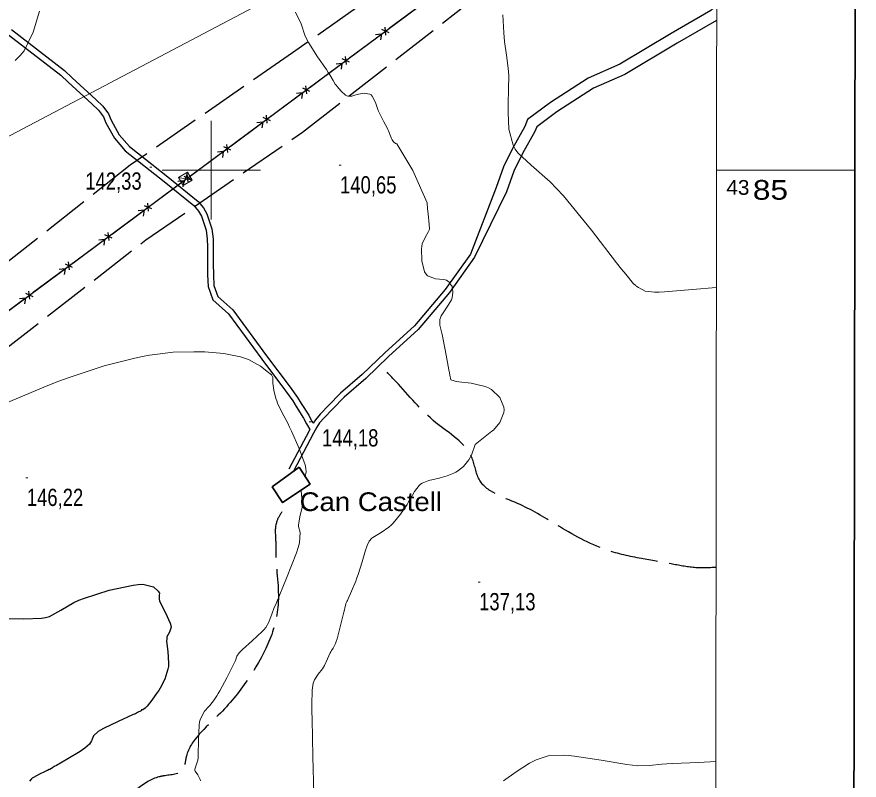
# Model space of a CAD drawing. Extents: x 487425 to 492029, y 4383576 to 4386788.
# Drawn here: x 490901.3 to 491328.9, y 4384690.4 to 4385077.8 of the extents above; entities that cross this region are included whole.
import ezdxf

# ---------------------------------------------------------------- set-up
doc = ezdxf.new("R2010")
doc.units = 0
doc.header["$LTSCALE"] = 4
doc.linetypes.add('DOTTED', pattern=[1.5, 0.3, -1.2])
doc.linetypes.add('LONG_DASHED', pattern=[7.5, 6, -1.5])
for name, color, linetype, lineweight in [('1', 7, 'Continuous', 13), ('2', 7, 'DOTTED', 13), ('24', 7, 'Continuous', 13), ('26', 7, 'LONG_DASHED', 25), ('27', 7, 'Continuous', 25), ('38', 7, 'Continuous', 25), ('43', 7, 'Continuous', 25), ('47', 7, 'Continuous', 35), ('7', 7, 'Continuous', 13), ('8', 7, 'Continuous', 25), ('9', 7, 'Continuous', 13)]:
    doc.layers.add(name, color=color, linetype=linetype, lineweight=lineweight)
doc.layers.add('5', color=7, linetype='Continuous')

msp = doc.modelspace()

# ---------------------------------------------------------------- linework, layer by layer
at = {"layer": '1'}
for p, q in [((491000, 4385025), (491000, 4384975)), ((490975, 4385000), (491025, 4385000)), ((491256.46, 4385000), (491326.67, 4385000))]:
    msp.add_line(p, q, dxfattribs=at)
at = {"layer": '1', "lineweight": 35}
msp.add_lwpolyline([(487611.46, 4386512.7), (491328.86, 4386507.3), (491325.3, 4384052.3), (487607.9, 4384057.7)], close=True, dxfattribs=at)
at = {"layer": '1'}
msp.add_lwpolyline([(487681.9, 4386441.2), (491258.2, 4386436), (491255.4, 4384123.8), (487678, 4384129)], close=True, dxfattribs=at)
at = {"layer": '24'}
msp.add_lwpolyline([(488954.49, 4384817.11), (489198.5, 4384851.16), (489357.39, 4384873.86), (489601.4, 4384907.91), (489794.34, 4384879.53), (490083.75, 4384822.79), (490248.31, 4384800.09), (490395.85, 4384817.11), (490526.37, 4384822.79), (490764.71, 4384947.63), (491088.16, 4385117.87), (491252.72, 4385202.99), (491256.7, 4385199.2)], dxfattribs=at)
at = {"layer": '26'}
for points in [[(491256.66, 4385212.94), (491193.79, 4385169.68), (491122.92, 4385116.81), (491041.24, 4385059.54), (490958.82, 4385002.51), (490860.74, 4384924.98), (490760.29, 4384859), (490692.5, 4384806.79), (490609.37, 4384741.58), (490560.51, 4384697.87)], [(490600.09, 4384693.63), (490616.48, 4384709.55), (490676.36, 4384751.65), (490767.73, 4384815.34), (490869.55, 4384889.03), (490966.8, 4384964.62), (491046.3, 4385019.26), (491131.3, 4385085.44), (491213.14, 4385147.42), (491256.63, 4385183.39)]]:
    msp.add_lwpolyline(points, dxfattribs=at)
at = {"layer": '27'}
msp.add_spline([(490552.62, 4384941.58), (490554.42, 4384943.67), (490554.9, 4384950.57), (490551.02, 4384958.75), (490549.23, 4384963.11), (490546.55, 4384969.04), (490546.27, 4384975.56), (490577.59, 4384991.51), (490608.31, 4385010.39), (490640.99, 4385029.26), (490675.61, 4385047.83), (490715.19, 4385070.58), (490756.65, 4385095.72), (490790.53, 4385116.54), (490822.22, 4385132.71), (490831.7, 4385141.3), (490834.32, 4385140.92), (490836.94, 4385139.04), (490838.42, 4385134.39), (490839.83, 4385127.26), (490841.17, 4385124.33), (490843.93, 4385120.95), (490854.88, 4385120.69), (490881, 4385131.56), (490910.74, 4385145.49), (490944, 4385160.61), (490977.26, 4385174.31), (491011.8, 4385191.9), (491038.91, 4385205.09), (491047.85, 4385210.16), (491048.16, 4385215.03), (491046.15, 4385220.51), (491027.8, 4385249.96), (491013.09, 4385271.3), (490994.07, 4385304.34), (490984.67, 4385319.67), (490979.29, 4385327.18), (490976.61, 4385330.57), (490974.75, 4385335.52), (490975.45, 4385343.54), (490977.85, 4385344.21), (490979.42, 4385344.13), (490980.47, 4385343.6), (490983.46, 4385341.64), (490988.77, 4385336.68), (490990.42, 4385334.95), (490993.78, 4385332.31), (491019.1, 4385348.81), (491045.47, 4385366.05), (491074.68, 4385380.36), (491106.91, 4385400.5), (491123.13, 4385410.28), (491127.87, 4385413.64), (491130.35, 4385415.43), (491144.45, 4385391.54), (491161.89, 4385359.02), (491165.47, 4385353.38)], degree=3, dxfattribs=at)
at = {"layer": '38'}
msp.add_line((491256.55, 4385076.09), (491256.5, 4385076.06), dxfattribs=at)
at = {"layer": '38', "linetype": 'LONG_DASHED'}
msp.add_line((491256.22, 4384798.37), (491256.18, 4384798.37), dxfattribs=at)
at = {"layer": '38'}
for points in [[(491256.51, 4385083.6), (491253.58, 4385080.97), (491233.52, 4385069.4), (491207.31, 4385053.73), (491191.24, 4385046.65), (491172.24, 4385034.32), (491160.59, 4385025.73), (491159.08, 4385022.14), (491152.98, 4385011.06), (491148.38, 4385001.69), (491144.6, 4384991.28), (491131.52, 4384957.38)], [(491256.5, 4385076.06), (491236.41, 4385064.48), (491209.94, 4385048.65), (491193.96, 4385041.61), (491175.49, 4385029.62), (491165.24, 4385022.07), (491164.23, 4385019.65), (491158.04, 4385008.42), (491153.64, 4384999.45), (491149.87, 4384989.08), (491133.68, 4384955.85)], [(490897.13, 4385068.75), (490923.56, 4385048.25), (490927.33, 4385044.69), (490939.3, 4385033.62), (490942.72, 4385030.49), (490945.27, 4385027.07), (490946.42, 4385024.1), (490950.8, 4385016.28), (490956.38, 4385009.82), (490976.15, 4384994.3), (490991.21, 4384982.07), (490993.58, 4384979.12), (490995.08, 4384976.58), (490997.36, 4384969.51), (490997.99, 4384965), (490998.05, 4384961.14), (490998.02, 4384952.51), (490998.15, 4384946.85), (490998.37, 4384940.92), (491000.74, 4384934.18), (491008.76, 4384927.03), (491025.62, 4384904), (491037.64, 4384888), (491041.34, 4384883.01), (491043.17, 4384880.06), (491046.87, 4384874.18), (491048.36, 4384871.24), (491048.89, 4384870.42), (491049.95, 4384868.3)], [(490898.54, 4385071.43), (490925.51, 4385050.53), (490929.37, 4385046.87), (490941.33, 4385035.82), (490944.94, 4385032.5), (490947.91, 4385028.54), (490949.14, 4385025.37), (490953.26, 4385018.01), (490958.45, 4385011.99), (490978.02, 4384996.64), (490993.34, 4384984.19), (490996.04, 4384980.83), (490997.82, 4384977.81), (491000.28, 4384970.18), (491000.97, 4384965.24), (491001.04, 4384961.16), (491001.01, 4384952.53), (491001.14, 4384946.94), (491001.34, 4384941.48), (491003.3, 4384935.9), (491010.98, 4384929.05), (491028.02, 4384905.78), (491040.04, 4384889.79), (491043.82, 4384884.69), (491045.71, 4384881.65), (491049.47, 4384875.65), (491050.96, 4384872.73), (491051.49, 4384871.91), (491051.68, 4384871.52)], [(491131.52, 4384957.38), (491118.79, 4384939.48), (491103.11, 4384920.97), (491088.13, 4384907.29), (491076.63, 4384896.3), (491065.65, 4384886.74), (491059.57, 4384880.62), (491055.29, 4384876.14), (491052.84, 4384873.33), (491051.68, 4384871.52)], [(491133.68, 4384955.85), (491120.88, 4384937.86), (491105.01, 4384919.14), (491089.94, 4384905.36), (491078.41, 4384894.34), (491067.46, 4384884.81), (491061.47, 4384878.78), (491057.24, 4384874.36), (491054.96, 4384871.74), (491053.58, 4384869.58), (491051.97, 4384866.47), (491041.78, 4384847.27)], [(491049.95, 4384868.3), (491049.63, 4384867.69), (491039.3, 4384848.23)]]:
    msp.add_lwpolyline(points, dxfattribs=at)
at = {"layer": '38', "linetype": 'LONG_DASHED'}
for points in [[(491256.18, 4384798.37), (491245.31, 4384798.29), (491233.39, 4384800.2), (491218.33, 4384802.87), (491200.79, 4384807.19), (491175.26, 4384820), (491155.42, 4384830.86), (491135.95, 4384843.13), (491132.38, 4384853.79), (491114.06, 4384871.84), (491093.74, 4384892.75), (491085.55, 4384901.17)], [(491035.82, 4384826.67), (491033.03, 4384821.06), (491032.7, 4384811.46), (491032.75, 4384805.46), (491033.95, 4384779.44), (491018.46, 4384741.32), (491003.56, 4384723.37), (490987.38, 4384702.58), (490986.77, 4384699.58), (490985.71, 4384695.91), (490975.88, 4384692.57), (490973.4, 4384692.05), (490953.04, 4384677.86), (490930.42, 4384660.99), (490909.59, 4384640.2), (490904.93, 4384636.47), (490898.54, 4384632.29), (490888.33, 4384629.1), (490882.71, 4384628.36), (490878.43, 4384627.48), (490868.68, 4384627.13)]]:
    msp.add_spline(points, degree=3, dxfattribs=at)
at = {"layer": '43'}
for p, q in [((491090.34, 4385072.02), (491106.4, 4385083.94)), ((491088.65, 4385068.6), (491088.19, 4385072.57)), ((491070.27, 4385057.12), (491086.33, 4385069.04)), ((491086.41, 4385069.1), (491083.42, 4385068.76)), ((491086.41, 4385069.1), (491085.97, 4385066.14)), ((491090.25, 4385069.79), (491086.58, 4385071.38)), ((491070.18, 4385054.89), (491066.51, 4385056.48)), ((491068.57, 4385053.7), (491068.12, 4385057.67)), ((491050.2, 4385042.22), (491066.26, 4385054.14)), ((491066.33, 4385054.2), (491063.35, 4385053.85)), ((491066.33, 4385054.2), (491065.89, 4385051.23)), ((491048.5, 4385038.79), (491048.05, 4385042.76)), ((491030.13, 4385027.32), (491046.19, 4385039.24)), ((491046.26, 4385039.3), (491043.28, 4385038.95)), ((491046.26, 4385039.3), (491045.82, 4385036.33)), ((491050.11, 4385039.99), (491046.44, 4385041.57)), ((491030.04, 4385025.08), (491026.37, 4385026.67)), ((491028.43, 4385023.89), (491027.97, 4385027.86)), ((491010.06, 4385012.42), (491026.12, 4385024.34)), ((491026.19, 4385024.39), (491023.21, 4385024.05)), ((491026.19, 4385024.39), (491025.75, 4385021.43)), ((491008.36, 4385008.99), (491007.9, 4385012.96)), ((490989.99, 4384997.52), (491006.05, 4385009.44)), ((491006.12, 4385009.49), (491003.13, 4385009.14)), ((491006.12, 4385009.49), (491005.68, 4385006.52)), ((491009.96, 4385010.18), (491006.3, 4385011.77)), ((490989.89, 4384995.28), (490986.22, 4384996.86)), ((490988.29, 4384994.08), (490987.83, 4384998.05)), ((490969.9, 4384982.64), (490985.98, 4384994.54)), ((490986.04, 4384994.59), (490983.06, 4384994.25)), ((490986.04, 4384994.59), (490985.6, 4384991.62)), ((490968.19, 4384979.2), (490967.74, 4384983.18)), ((490949.81, 4384967.76), (490965.88, 4384979.66)), ((490965.95, 4384979.71), (490962.97, 4384979.37)), ((490965.95, 4384979.71), (490965.51, 4384976.74)), ((490969.8, 4384980.39), (490966.13, 4384981.98)), ((490949.71, 4384965.52), (490946.04, 4384967.11)), ((490948.1, 4384964.33), (490947.65, 4384968.3)), ((490929.72, 4384952.89), (490945.79, 4384964.79)), ((490945.86, 4384964.83), (490942.88, 4384964.49)), ((490945.86, 4384964.83), (490945.42, 4384961.87)), ((490928.01, 4384949.45), (490927.56, 4384953.42)), ((490909.63, 4384938.02), (490925.7, 4384949.92)), ((490925.77, 4384949.95), (490922.79, 4384949.61)), ((490925.77, 4384949.95), (490925.33, 4384946.99)), ((490929.62, 4384950.64), (490925.95, 4384952.23)), ((490909.53, 4384935.76), (490905.86, 4384937.35)), ((490907.92, 4384934.57), (490907.47, 4384938.54)), ((490889.54, 4384923.14), (490905.61, 4384935.04)), ((490905.68, 4384935.08), (490902.7, 4384934.73)), ((490905.68, 4384935.08), (490905.24, 4384932.11))]:
    msp.add_line(p, q, dxfattribs=at)
at = {"layer": '43', "lineweight": 13}
for p, q in [((490983.38, 4384996.27), (490990.28, 4384994.92)), ((490985.78, 4384992.24), (490987.88, 4384998.95))]:
    msp.add_line(p, q, dxfattribs=at)
at = {"layer": '43'}
msp.add_lwpolyline([(489809.89, 4384125.9), (490053.43, 4384305.98), (490295.56, 4384486.1), (490534.15, 4384662.33), (490743.89, 4384815.26), (490986.91, 4384995.23), (491244.37, 4385186.39)], dxfattribs=at)
at = {"layer": '43', "lineweight": 13}
msp.add_lwpolyline([(490985.78, 4384992.24), (490983.38, 4384996.27), (490987.88, 4384998.95), (490990.28, 4384994.92)], close=True, dxfattribs=at)
at = {"layer": '47'}
msp.add_lwpolyline([(491044.58, 4384849.29), (491030.98, 4384839.21), (491036.21, 4384831.25), (491050.18, 4384840.65)], close=True, dxfattribs=at)
at = {"layer": '7'}
for p, q in [((490968.81, 4385001.5), (490969.81, 4385001.5)), ((491064.87, 4385002.56), (491065.87, 4385002.56)), ((491049.7, 4384872.29), (491050.7, 4384872.29)), ((490905.88, 4384843.93), (490906.88, 4384843.93)), ((491135.46, 4384790.98), (491136.46, 4384790.98))]:
    msp.add_line(p, q, dxfattribs=at)
at = {"layer": '8'}
for points in [[(490894.96, 4384772.44), (490904.9, 4384772.35), (490913.82, 4384772.59), (490915.93, 4384772.98), (490917.89, 4384773.51), (490923.65, 4384776.6), (490930.29, 4384780.59), (490932.8, 4384781.69), (490935.6, 4384782.8), (490948.12, 4384786.76), (490960.35, 4384789.45), (490962.96, 4384789.75), (490965.24, 4384789.85), (490970.67, 4384788.6), (490973.08, 4384786.38), (490973.46, 4384785.88), (490973.71, 4384785.42), (490973.57, 4384784.17), (490973.48, 4384782.23), (490973.75, 4384781.34), (490974.16, 4384780.3), (490976.74, 4384775.25), (490979.14, 4384770.08), (490979.44, 4384768.96), (490979.59, 4384767.98), (490978.78, 4384765.56), (490977.53, 4384763.1), (490977.39, 4384762.09), (490977.33, 4384760.94), (490977.89, 4384755.64), (490978.35, 4384749.71), (490978.24, 4384748.17), (490978.03, 4384746.68), (490976.4, 4384741.66), (490974, 4384737.15), (490973.31, 4384735.98), (490972.59, 4384734.83), (490969.9, 4384730.97), (490967.5, 4384728.01), (490966.98, 4384727.44), (490966.51, 4384726.97)], [(490966.51, 4384726.97), (490965.31, 4384726.16), (490964.66, 4384726.02), (490964.55, 4384725.97), (490964.46, 4384725.91), (490964.36, 4384725.67), (490962.61, 4384724.67), (490961.49, 4384724.14), (490960.09, 4384723.49), (490952.71, 4384720.21), (490945.22, 4384716.65), (490943.74, 4384715.83), (490942.52, 4384715.07), (490940.29, 4384712.91), (490939.63, 4384711.22), (490939.4, 4384710.76), (490939.15, 4384710.31), (490938.11, 4384708.68), (490935.74, 4384706.57), (490934.66, 4384705.81), (490933.39, 4384704.96), (490927.27, 4384701.29), (490921.4, 4384697.91), (490920.29, 4384697.27), (490919.4, 4384696.74), (490918.07, 4384695.89), (490918.11, 4384695.84), (490918.08, 4384695.82), (490918.05, 4384695.81), (490917.8, 4384695.73), (490916.82, 4384695.33), (490916.32, 4384695.1), (490915.72, 4384694.83), (490912.73, 4384693.41), (490909.75, 4384691.82), (490909.16, 4384691.43), (490908.68, 4384691.06), (490907.76, 4384689.92)]]:
    msp.add_lwpolyline(points, dxfattribs=at)
at = {"layer": '9'}
for p, q in [((491256.34, 4384940.46), (491256.39, 4384940.46)), ((491256.06, 4384699.88), (491256.1, 4384699.88))]:
    msp.add_line(p, q, dxfattribs=at)
for points in [[(490900.47, 4385055.74), (490902.95, 4385058.14), (490905.05, 4385060.62), (490909.62, 4385070.13), (490912.85, 4385080.69)], [(491042.78, 4385080.28), (491045.6, 4385074.26), (491047.57, 4385068.47), (491048.41, 4385066.7), (491049.37, 4385064.86), (491053.92, 4385057.6), (491058.41, 4385051.06), (491059.34, 4385049.66), (491060.13, 4385048.45), (491061.84, 4385045.59), (491062.97, 4385043.73), (491063.39, 4385043.15), (491063.85, 4385042.54), (491065.91, 4385040.11), (491068.16, 4385038.14), (491068.75, 4385037.82), (491069.33, 4385037.59), (491071.27, 4385037.59), (491073.38, 4385038.19), (491074.06, 4385038.35), (491074.77, 4385038.51), (491077.69, 4385039.06), (491080.49, 4385038.66), (491081.14, 4385038.23), (491081.72, 4385037.65), (491083.36, 4385034.39), (491084.78, 4385030.35), (491085.22, 4385029.28), (491085.68, 4385028.23), (491087.55, 4385024.61), (491089.29, 4385021.44), (491089.67, 4385020.68), (491090.02, 4385019.97), (491090.89, 4385017.81), (491091.51, 4385016.16), (491091.68, 4385015.77), (491091.86, 4385015.41), (491092.52, 4385014.34), (491093.44, 4385013.63), (491093.79, 4385013.51), (491094.18, 4385013.41)], [(491147.98, 4385078.89), (491148.48, 4385069.78), (491148.68, 4385067.5), (491148.9, 4385065.32), (491149.9, 4385058.3), (491150.76, 4385051.81), (491150.89, 4385049.96), (491150.97, 4385048.08), (491150.89, 4385041.11), (491150.69, 4385033.66), (491150.7, 4385031.49), (491150.73, 4385029.27), (491151.1, 4385020.86), (491153.17, 4385012.75), (491154.28, 4385010.72), (491155.62, 4385008.79), (491162.38, 4385002.6), (491172.1, 4384994.15), (491175.3, 4384990.79), (491178.72, 4384986.99), (491192.93, 4384969.58), (491205.73, 4384953.06), (491208.27, 4384949.81), (491210.38, 4384947.14), (491214.35, 4384942.32), (491215.43, 4384941.39), (491215.71, 4384941.17), (491215.99, 4384940.97), (491216.94, 4384940.42), (491217.99, 4384939.86), (491218.34, 4384939.67), (491218.7, 4384939.46), (491220.21, 4384938.55), (491224.91, 4384938.06), (491227.29, 4384938.11), (491230.14, 4384938.25)], [(491094.18, 4385013.41), (491102.37, 4384999.82), (491109.63, 4384983.44), (491109.83, 4384980.36), (491110.03, 4384977.77), (491110.66, 4384972.46), (491110.7, 4384970.19), (491110.53, 4384969.53), (491110.27, 4384968.84), (491108.68, 4384966.24), (491107.11, 4384962.69), (491106.86, 4384961.42), (491106.71, 4384960.03), (491106.83, 4384953.93), (491108.31, 4384948.34), (491109.01, 4384947.26), (491109.84, 4384946.38), (491113.86, 4384944.9), (491117.85, 4384944.54), (491118.66, 4384944.38), (491119.34, 4384944.18), (491120.72, 4384943.22), (491121.22, 4384942.26), (491121.35, 4384942.06), (491121.47, 4384941.9), (491121.86, 4384941.55), (491122.2, 4384940.91), (491122.29, 4384940.57), (491122.37, 4384940.15), (491122.66, 4384938.02), (491122.26, 4384935.16), (491121.92, 4384934.28), (491121.47, 4384933.36), (491119.03, 4384929.71), (491116.69, 4384926.05), (491116.31, 4384925.12), (491116.05, 4384924.23), (491116.09, 4384921.31), (491117.06, 4384917.35), (491117.38, 4384915.8), (491117.73, 4384914.06), (491119.21, 4384906.13), (491120.58, 4384898.61), (491120.86, 4384897.13), (491121.1, 4384895.9), (491121.61, 4384893.63), (491123.34, 4384893), (491124.35, 4384892.81), (491125.59, 4384892.62), (491131.99, 4384891.84), (491139.02, 4384890.23), (491140.66, 4384889.51), (491142.16, 4384888.67), (491146.47, 4384884.62), (491148.56, 4384879.74), (491148.66, 4384878.37), (491148.55, 4384877), (491146.44, 4384871.95), (491143.19, 4384868.09), (491142.37, 4384867.46), (491133.96, 4384860.81), (491132.07, 4384855.42), (491131.45, 4384854.15), (491130.79, 4384852.99), (491128.06, 4384849.64), (491124.97, 4384847.26), (491124.08, 4384846.71), (491123.17, 4384846.22), (491119.78, 4384844.84), (491116.24, 4384843.85), (491115.23, 4384843.59), (491114.22, 4384843.35), (491110.48, 4384842.54), (491107.04, 4384841.2), (491106.22, 4384840.63), (491105.46, 4384839.97)], [(491230.14, 4384938.25), (491244.31, 4384939.4), (491256.34, 4384940.46)], [(490895.79, 4384881.71), (490917.1, 4384890.74), (490922.6, 4384892.87), (490927.92, 4384894.84), (490945.67, 4384900.64), (490961.14, 4384904.6), (490965.02, 4384905.41), (490968.73, 4384906.1), (490980.68, 4384907.56), (490991.2, 4384907.86), (490994.01, 4384907.82), (490996.77, 4384907.72), (491006.36, 4384906.93), (491014.87, 4384905.25), (491016.94, 4384904.6), (491018.9, 4384903.87), (491024.95, 4384900.57), (491029.13, 4384897.35), (491029.9, 4384896.67), (491030.51, 4384896.09)], [(491030.51, 4384896.09), (491031.29, 4384894.76), (491031.18, 4384893.35), (491031.21, 4384892.72), (491031.28, 4384891.98), (491031.74, 4384888.43), (491032.78, 4384884.12), (491033.2, 4384882.91), (491033.67, 4384881.68), (491035.88, 4384877.14), (491038.8, 4384871.52), (491039.72, 4384869.6), (491040.69, 4384867.52), (491044.62, 4384858.73), (491047.63, 4384850.37), (491048.03, 4384848.56), (491048.23, 4384846.98), (491047.68, 4384844.5)], [(491045.61, 4384837.57), (491045.81, 4384835.05), (491046.24, 4384831.09), (491046.21, 4384829.99), (491046.11, 4384828.87), (491045.2, 4384824.82), (491044.37, 4384820.99), (491044.32, 4384820.02), (491044.34, 4384819.09), (491045.06, 4384816.07), (491044.75, 4384810.83), (491044.13, 4384808.51), (491043.28, 4384805.8), (491038.25, 4384792.86), (491032.9, 4384780.07), (491031.83, 4384777.46), (491030.95, 4384775.24), (491029.27, 4384770.59), (491027.67, 4384767.91), (491026.83, 4384766.94), (491025.82, 4384765.86), (491020.74, 4384761.14), (491015.79, 4384756.68), (491014.85, 4384755.76), (491014.11, 4384754.98), (491013.01, 4384753.33), (491012.3, 4384751.19), (491011.8, 4384750.11), (491011.18, 4384748.81), (491007.84, 4384742.35), (491004.27, 4384735.77), (491003.5, 4384734.4), (491002.83, 4384733.23), (491001.18, 4384730.6), (490999.84, 4384728.98), (490999.36, 4384728.43), (490998.83, 4384727.85), (490996.52, 4384725.39), (490994.46, 4384721.47), (490994.08, 4384719.97), (490993.79, 4384718.28), (490993.45, 4384710.69), (490993.39, 4384703.33), (490993.27, 4384701.8), (490993.12, 4384700.49), (490992.21, 4384697.57), (490991.63, 4384695.97), (490991.68, 4384695.5), (490991.82, 4384695), (490993.12, 4384693.09), (490994.4, 4384690.77), (490994.54, 4384690.01)], [(491105.46, 4384839.97), (491103.17, 4384836.84), (491100.91, 4384832.84), (491100.17, 4384831.63), (491099.37, 4384830.38), (491096.04, 4384825.49), (491092.3, 4384820.9), (491091.24, 4384819.83), (491090.16, 4384818.86), (491086.19, 4384816.08), (491082.79, 4384814.09), (491082.08, 4384813.61), (491081.47, 4384813.16), (491080.1, 4384811.79), (491079.13, 4384809.46), (491078.77, 4384808.41), (491078.36, 4384807.19), (491076.59, 4384801.3), (491074.52, 4384794.71), (491073.94, 4384793.04), (491073.35, 4384791.44), (491071.18, 4384786.25), (491069.41, 4384782.41), (491069.07, 4384781.67), (491068.8, 4384781.07), (491068.37, 4384780.07), (491068.35, 4384779.95), (491068.34, 4384779.92), (491068.33, 4384779.88), (491068.27, 4384779.71), (491067.82, 4384777.95), (491067.56, 4384776.9), (491067.25, 4384775.62), (491065.63, 4384768.97), (491063.85, 4384762.2), (491063.43, 4384760.84), (491063.05, 4384759.7), (491061.95, 4384757.47), (491060.98, 4384756.15), (491060.67, 4384755.59), (491060.35, 4384754.95), (491059.06, 4384751.95), (491057.49, 4384748.59), (491056.99, 4384747.73), (491056.46, 4384746.9), (491054.33, 4384744.12), (491052.44, 4384741.32), (491052.06, 4384740.46), (491051.74, 4384739.57), (491051.14, 4384736.08), (491051.07, 4384728.67), (491051.1, 4384725.3), (491051.15, 4384721.37), (491051.5, 4384702.45), (491052.02, 4384683.38)], [(491148.28, 4384690.14), (491154.76, 4384694.62), (491161.48, 4384698.95), (491163.25, 4384699.88), (491164.99, 4384700.7), (491170.96, 4384702.69), (491178.57, 4384703.12), (491181.34, 4384702.94), (491184.4, 4384702.65), (491197.85, 4384700.52), (491210.96, 4384698.33), (491213.8, 4384697.98), (491216.3, 4384697.75), (491222.48, 4384697.86), (491228.7, 4384698.6), (491231.22, 4384698.77), (491234.09, 4384698.93), (491247.34, 4384699.35), (491256.06, 4384699.88)]]:
    msp.add_lwpolyline(points, dxfattribs=at)

# ---------------------------------------------------------------- texts
at = {"layer": '2'}
for s, height, width, p in [('43', 7.5, 1.05, (491261.45, 4384987.5)), ('85  ', 10, 1.2, (491274.9, 4384985))]:
    msp.add_text(s, height=height, dxfattribs=dict(at, width=width)).set_placement(p)
at = {"layer": '5', "width": 1.1}
msp.add_text('Can Castell', height=9.5, dxfattribs=at).set_placement((491044.87, 4384826.99))
at = {"layer": '7', "width": 0.8}
for s, p in [('142,33', (490936.05, 4384990.12)), ('140,65', (491065.37, 4384988.19)), ('144,18', (491056.21, 4384859.77)), ('146,22', (490906.38, 4384829.56)), ('137,13', (491135.96, 4384776.61))]:
    msp.add_text(s, height=8.75, dxfattribs=at).set_placement(p)

doc.saveas('drawing.dxf')
